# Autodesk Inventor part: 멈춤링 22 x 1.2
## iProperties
IsCustomPart: 0
Company: 한국ATC센터
Created: 2009-02
Part Number: 멈춤링 22 x 1.2
Material: Steel, Mild
Description: 리테이닝 링(C형)
Document SubType Name: Modeling
Standard: KS B 1336
Designer: KYOUNG IL JANG
Standards Organization: KS
Language: ko-KR
Size Designation: 22 x 1.2
Categories: <MemberInstance><Categories><Category DisplayName="샤프트 부품" InternalName="7f7aeb1f-a693-4053-b835-cee3144e0d98" Mnemonic="SHFT"><Category DisplayName="써클립" Inter
Density: 7.86 g/cm^3
Mass: 1.82859 g
Surface Area: 5.91219 cm^2
Volume: 0.232645 cm^3
Author: KYOUNG IL JANG
